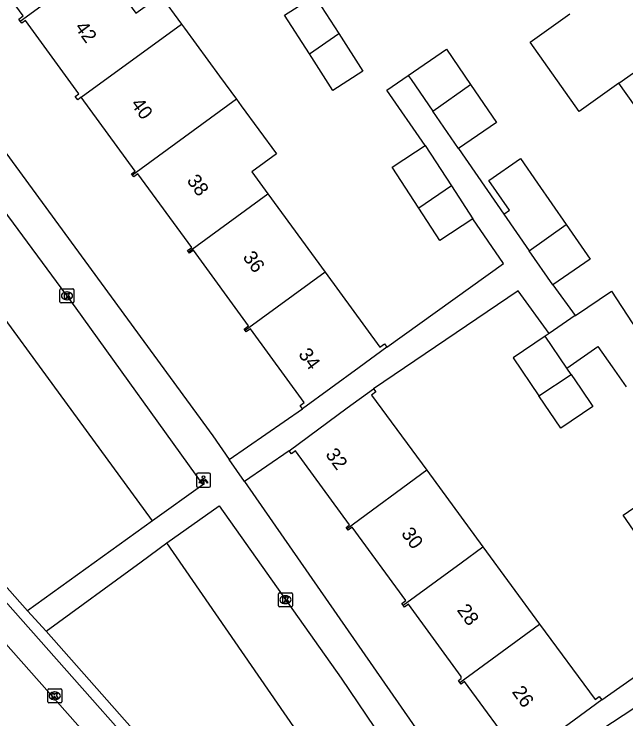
# Model space of a CAD drawing. Extents: x 157466 to 158888, y 383063 to 384677.
# Drawn here: x 157968.1 to 158011.8, y 383507.6 to 383558 of the extents above; entities that cross this region are included whole.
import ezdxf

# ---------------------------------------------------------------- set-up
doc = ezdxf.new("R2010")
doc.units = 0
for name, color, linetype in [('IMGEO_Groenvoorziening', 7, 'Continuous'), ('IMGEO_Kolk', 7, 'Continuous'), ('IMGEO_Lichtpunt', 7, 'Continuous'), ('IMGEO_Pand', 7, 'Continuous'), ('IMGEO_Pand_nummerreeks', 7, 'Continuous'), ('IMGEO_Rijbaan_lokaal_gesloten', 7, 'Continuous'), ('IMGEO_Voetpad_open', 7, 'Continuous')]:
    doc.layers.add(name, color=color, linetype=linetype)

msp = doc.modelspace()

# ---------------------------------------------------------------- linework, layer by layer
at = {"layer": 'IMGEO_Groenvoorziening'}
for points in [[(157977.961, 383521.773), (157959.54, 383546.985)], [(157993.986, 383498.111), (157992.947, 383500), (157978.989, 383520.199)]]:
    msp.add_lwpolyline(points, dxfattribs=at)
at = {"layer": 'IMGEO_Kolk'}
for p, q in [((157971.352, 383537.425), (157971.352, 383538.277)), ((157971.427, 383538.351), (157972.279, 383538.351)), ((157972.353, 383538.277), (157972.353, 383537.425)), ((157971.84, 383538.131), (157971.865, 383538.131)), ((157972.279, 383537.351), (157971.427, 383537.351)), ((157971.863, 383537.571), (157971.838, 383537.571)), ((157986.956, 383515.719), (157986.956, 383516.571)), ((157987.031, 383516.645), (157987.883, 383516.645)), ((157987.957, 383516.571), (157987.957, 383515.719)), ((157987.444, 383516.425), (157987.469, 383516.425)), ((157987.883, 383515.645), (157987.031, 383515.645)), ((157987.467, 383515.865), (157987.442, 383515.865)), ((157970.478, 383508.854), (157970.478, 383509.706)), ((157970.553, 383509.78), (157971.405, 383509.78)), ((157970.966, 383509.56), (157970.991, 383509.56)), ((157971.479, 383509.706), (157971.479, 383508.854)), ((157970.989, 383509), (157970.964, 383509)), ((157971.405, 383508.78), (157970.553, 383508.78))]:
    msp.add_line(p, q, dxfattribs=at)
for points in [[(157971.352, 383537.425), (157971.352, 383538.277)], [(157971.427, 383538.351), (157972.279, 383538.351)], [(157972.353, 383538.277), (157972.353, 383537.425)], [(157971.673, 383538.051), (157971.796, 383538.051), (157971.796, 383537.9), (157971.926, 383538.051), (157972.09, 383538.051), (157971.944, 383537.9), (157972.097, 383537.651), (157971.945, 383537.651), (157971.86, 383537.815), (157971.796, 383537.748), (157971.796, 383537.651), (157971.673, 383537.651), (157971.673, 383538.051)], [(157972.279, 383537.351), (157971.427, 383537.351)], [(157986.956, 383515.719), (157986.956, 383516.571)], [(157987.031, 383516.645), (157987.883, 383516.645)], [(157987.957, 383516.571), (157987.957, 383515.719)], [(157987.277, 383516.345), (157987.4, 383516.345), (157987.4, 383516.194), (157987.53, 383516.345), (157987.694, 383516.345), (157987.548, 383516.194), (157987.701, 383515.945), (157987.549, 383515.945), (157987.464, 383516.109), (157987.4, 383516.042), (157987.4, 383515.945), (157987.277, 383515.945), (157987.277, 383516.345)], [(157987.883, 383515.645), (157987.031, 383515.645)], [(157970.478, 383508.854), (157970.478, 383509.706)], [(157970.553, 383509.78), (157971.405, 383509.78)], [(157971.479, 383509.706), (157971.479, 383508.854)], [(157970.799, 383509.48), (157970.922, 383509.48), (157970.922, 383509.329), (157971.052, 383509.48), (157971.216, 383509.48), (157971.07, 383509.329), (157971.223, 383509.08), (157971.071, 383509.08), (157970.986, 383509.244), (157970.922, 383509.177), (157970.922, 383509.08), (157970.799, 383509.08), (157970.799, 383509.48)], [(157971.405, 383508.78), (157970.553, 383508.78)]]:
    msp.add_lwpolyline(points, dxfattribs=at)
for centre, start, end in [((157971.429, 383538.275), 91.552, 178.448), ((157971.429, 383538.275), 91.552, 178.448), ((157972.277, 383538.275), 1.552, 88.448), ((157972.277, 383538.275), 1.552, 88.448), ((157971.429, 383537.427), 181.552, 268.448), ((157971.429, 383537.427), 181.552, 268.448), ((157972.277, 383537.427), 271.552, 358.448), ((157972.277, 383537.427), 271.552, 358.448), ((157987.033, 383516.569), 91.552, 178.448), ((157987.033, 383516.569), 91.552, 178.448), ((157987.881, 383516.569), 1.552, 88.448), ((157987.881, 383516.569), 1.552, 88.448), ((157987.033, 383515.721), 181.552, 268.448), ((157987.033, 383515.721), 181.552, 268.448), ((157987.881, 383515.721), 271.552, 358.448), ((157987.881, 383515.721), 271.552, 358.448), ((157970.555, 383509.704), 91.552, 178.448), ((157970.555, 383509.704), 91.552, 178.448), ((157971.403, 383509.704), 1.552, 88.448), ((157971.403, 383509.704), 1.552, 88.448), ((157970.555, 383508.856), 181.552, 268.448), ((157970.555, 383508.856), 181.552, 268.448), ((157971.403, 383508.856), 271.552, 358.448), ((157971.403, 383508.856), 271.552, 358.448)]:
    msp.add_arc(centre, 0.0765, start, end, dxfattribs=at)
for centre, major_axis, ratio, start_param, end_param in [((157971.839, 383537.851), (-0.387, 0.002), 0.722429, 4.712389, 7.853982), ((157971.864, 383537.851), (-0.39, 0.002), 0.717154, 1.570796, 4.712389), ((157987.443, 383516.145), (-0.387, 0.002), 0.722429, 4.712389, 7.853982), ((157987.468, 383516.145), (-0.39, 0.002), 0.717154, 1.570796, 4.712389), ((157970.965, 383509.28), (-0.387, 0.002), 0.722429, 4.712389, 7.853982), ((157970.99, 383509.28), (-0.39, 0.002), 0.717154, 1.570796, 4.712389)]:
    msp.add_ellipse(centre, major_axis=major_axis, ratio=ratio, start_param=start_param, end_param=end_param, dxfattribs=at)
at = {"layer": 'IMGEO_Lichtpunt'}
for p, q in [((157981.109, 383525.094), (157981.109, 383524.287)), ((157981.109, 383525.094), (157981.109, 383524.287)), ((157982.011, 383525.189), (157981.203, 383525.189)), ((157982.011, 383525.189), (157981.203, 383525.189)), ((157982.105, 383524.287), (157982.105, 383525.094)), ((157982.105, 383524.287), (157982.105, 383525.094)), ((157981.203, 383524.193), (157982.011, 383524.193)), ((157981.203, 383524.193), (157982.011, 383524.193))]:
    msp.add_line(p, q, dxfattribs=at)
for points in [[(157981.483, 383524.758), (157981.522, 383524.73), (157981.334, 383524.468), (157981.296, 383524.495), (157981.483, 383524.758)], [(157981.585, 383524.71), (157981.632, 383524.71), (157981.632, 383524.388), (157981.585, 383524.388), (157981.585, 383524.71)], [(157981.695, 383524.73), (157981.733, 383524.757), (157981.92, 383524.495), (157981.881, 383524.467), (157981.695, 383524.73)]]:
    msp.add_lwpolyline(points, dxfattribs=at)
msp.add_circle((157981.608, 383524.892), 0.0994, dxfattribs=at)
for centre, start, end in [((157981.203, 383525.094), 90, 180), ((157981.203, 383525.094), 90, 180), ((157982.011, 383525.094), 0, 90), ((157982.011, 383525.094), 0, 90), ((157981.203, 383524.287), 180, 270), ((157981.203, 383524.287), 180, 270), ((157982.011, 383524.287), 270, 0), ((157982.011, 383524.287), 270, 360)]:
    msp.add_arc(centre, 0.0946, start, end, dxfattribs=at)
at = {"layer": 'IMGEO_Pand'}
for points in [[(157968.52, 383557.477), (157968.413, 383557.623), (157968.717, 383557.846), (157964.929, 383563.029), (157964.634, 383562.813), (157964.565, 383562.908)], [(157968.52, 383557.477), (157974.169, 383561.61)], [(157974.169, 383561.61), (157976.773, 383558.046), (157978.527, 383559.328), (157980.031, 383557.27)], [(157989.167, 383555.142), (157987.386, 383557.912), (157989.528, 383559.29)], [(157989.711, 383559.006), (157991.269, 383556.582)], [(158011.275, 383553.039), (158008.447, 383551.029), (158004.933, 383555.973), (158007.768, 383557.989)], [(157972.866, 383552.045), (157972.617, 383551.863), (157972.447, 383552.096), (157972.706, 383552.286), (157968.884, 383557.516), (157968.628, 383557.329), (157968.52, 383557.477)], [(157972.866, 383552.045), (157980.031, 383557.27)], [(157980.031, 383557.27), (157980.246, 383556.975), (157982.754, 383553.543), (157983.959, 383551.895)], [(158011.275, 383553.039), (158016.758, 383556.936)], [(157991.269, 383556.582), (157992.993, 383553.901), (157990.85, 383552.523), (157989.167, 383555.142)], [(157989.167, 383555.142), (157991.269, 383556.582)], [(157996.23, 383553.598), (157998.95, 383555.464), (158000.677, 383552.948)], [(157996.23, 383553.598), (157996.427, 383553.311), (157997.987, 383551.036)], [(157997.987, 383551.036), (158000.677, 383552.948)], [(158000.677, 383552.948), (158002.536, 383550.238), (157999.816, 383548.371)], [(158014.764, 383548.114), (158011.275, 383553.039)], [(157976.542, 383546.469), (157976.462, 383546.579), (157976.722, 383546.768), (157972.866, 383552.045)], [(157983.959, 383551.895), (157976.542, 383546.469)], [(157983.959, 383551.895), (157984.302, 383551.426), (157986.81, 383547.993), (157985.056, 383546.712), (157986.201, 383545.145)], [(157999.816, 383548.371), (157997.987, 383551.036)], [(157996.99, 383544.113), (157995.076, 383547.05), (157996.749, 383548.141), (157997.435, 383548.588)], [(157997.435, 383548.588), (157999.314, 383545.704)], [(158003.058, 383543.695), (158003.448, 383543.965), (158001.98, 383546.087), (158004.247, 383547.656), (158005.457, 383545.909), (158007.504, 383542.953)], [(157980.522, 383540.99), (157980.454, 383541.083), (157980.765, 383541.311), (157976.92, 383546.573), (157976.624, 383546.357), (157976.542, 383546.469)], [(157999.314, 383545.704), (157996.99, 383544.113)], [(157999.314, 383545.704), (158000.852, 383543.345)], [(157980.522, 383540.99), (157986.201, 383545.145)], [(157986.201, 383545.145), (157990.292, 383539.548)], [(158000.852, 383543.345), (157998.493, 383541.808), (157996.99, 383544.113)], [(158003.058, 383543.695), (158004.869, 383541.079)], [(158004.869, 383541.079), (158007.504, 383542.953)], [(158007.504, 383542.953), (158009.22, 383540.473), (158006.563, 383538.633)], [(157984.572, 383535.378), (157984.498, 383535.48), (157984.821, 383535.716), (157980.882, 383541.106), (157980.592, 383540.894), (157980.522, 383540.99)], [(158006.563, 383538.633), (158004.869, 383541.079)], [(157990.292, 383539.548), (157984.572, 383535.378)], [(157990.292, 383539.548), (157994.208, 383534.189), (157994.526, 383534.422), (157994.698, 383534.186)], [(158008.161, 383536.443), (158008.183, 383536.458), (158010.734, 383538.188), (158012.229, 383535.933), (158014.218, 383533.078)], [(158008.161, 383536.443), (158006.281, 383535.17)], [(157988.678, 383529.787), (157988.501, 383530.029), (157988.794, 383530.244), (157984.952, 383535.501), (157984.646, 383535.277), (157984.572, 383535.378)], [(158006.281, 383535.17), (158006, 383534.979)], [(158006, 383534.979), (158003.719, 383533.433), (158005.559, 383530.717)], [(158007.558, 383532.68), (158006, 383534.979)], [(157994.698, 383534.186), (157992.716, 383532.737), (157988.678, 383529.787)], [(158007.558, 383532.68), (158009.779, 383534.227), (158010.782, 383532.788), (158011.784, 383531.348)], [(158007.856, 383532.24), (158007.558, 383532.68)], [(158005.559, 383530.717), (158007.856, 383532.24)], [(158007.856, 383532.24), (158008.522, 383531.257), (158009.41, 383529.946), (158007.128, 383528.4), (158005.559, 383530.717)], [(157987.723, 383526.79), (157991.876, 383529.842), (157993.741, 383531.213)], [(157993.741, 383531.213), (157993.909, 383530.985), (157993.608, 383530.764), (157997.548, 383525.395)], [(157991.856, 383521.213), (157991.783, 383521.313), (157992.043, 383521.504), (157988.173, 383526.772), (157987.882, 383526.558), (157987.723, 383526.79)], [(157997.548, 383525.395), (157991.856, 383521.213)], [(157997.548, 383525.395), (158000, 383522.053), (158001.555, 383519.934)], [(158013.353, 383519.593), (158011.575, 383522.191), (158014.242, 383524.015)], [(157995.861, 383515.751), (157995.764, 383515.883), (157996.058, 383516.099), (157992.217, 383521.327), (157991.928, 383521.115), (157991.856, 383521.213)], [(157995.861, 383515.751), (158000, 383518.792), (158001.555, 383519.934)], [(158001.555, 383519.934), (158005.612, 383514.405)], [(157999.919, 383510.224), (157999.805, 383510.379), (158000, 383510.522), (158000, 383510.669), (157996.234, 383515.822), (157995.958, 383515.619), (157995.861, 383515.751)], [(157999.919, 383510.224), (158005.612, 383514.405)], [(158005.612, 383514.405), (158009.571, 383509.009), (158009.87, 383509.228), (158010.049, 383508.984)], [(158004.038, 383504.58), (158003.858, 383504.825), (158004.127, 383505.022), (158000.257, 383510.302), (158000, 383510.114), (157999.919, 383510.224)], [(158010.049, 383508.984), (158008.072, 383507.536), (158004.038, 383504.58)]]:
    msp.add_lwpolyline(points, dxfattribs=at)
at = {"layer": 'IMGEO_Rijbaan_lokaal_gesloten'}
msp.add_lwpolyline([(157992.101, 383485.193), (157928.672, 383556.808)], dxfattribs=at)
at = {"layer": 'IMGEO_Voetpad_open'}
for points in [[(157929.336, 383596.06), (157933.255, 383591.676), (157962.879, 383554.327), (157965.119, 383551.269), (157982.271, 383527.85), (157983.448, 383526.155)], [(157930.01, 383558.3), (157983.378, 383498.016), (157992.065, 383488.205), (157997.202, 383482.054), (158000.095, 383477.951)], [(157997.435, 383548.588), (157994.703, 383552.543), (157996.23, 383553.598)], [(157959.54, 383546.985), (157963.112, 383549.668), (157972.494, 383536.982), (157981.567, 383524.365), (157977.961, 383521.773)], [(157999.816, 383548.371), (158003.058, 383543.695)], [(157994.698, 383534.186), (158003.037, 383540.171), (158000.852, 383543.345)], [(157969.04, 383515.361), (157948.437, 383538.644)], [(158006.281, 383535.17), (158004.089, 383538.223), (157993.741, 383531.213)], [(158006.563, 383538.633), (158008.161, 383536.443)], [(157983.448, 383526.155), (157988.678, 383529.787)], [(157987.723, 383526.79), (157984.541, 383524.581)], [(157984.541, 383524.581), (157983.448, 383526.155)], [(157984.541, 383524.581), (158000.328, 383501.854)], [(157978.989, 383520.199), (157982.718, 383522.845), (157991.425, 383510.532), (157998.027, 383500.773), (157996.836, 383500), (157993.986, 383498.111)], [(157977.961, 383521.773), (157969.04, 383515.361)], [(157970.368, 383513.905), (157977.144, 383518.851), (157978.989, 383520.199)], [(158010.049, 383508.984), (158019.772, 383515.834), (158017.816, 383518.792)], [(157970.368, 383513.905), (157969.04, 383515.361)], [(157987.894, 383494.074), (157970.368, 383513.905)], [(158012.33, 383508.373), (158009.303, 383506.368)]]:
    msp.add_lwpolyline(points, dxfattribs=at)

# ---------------------------------------------------------------- texts
at = {"layer": 'IMGEO_Pand_nummerreeks'}
for s, rotation, p in [('42', 306.1649, (157972.37, 383557.024)), ('40', 306.1649, (157976.372, 383551.548)), ('38', 306.1649, (157980.372, 383546.077)), ('36', 306.1665, (157984.368, 383540.607)), ('34', 306.3393, (157988.337, 383533.671)), ('32', 306.2756, (157990.275, 383526.523)), ('30', 306.3046, (157995.683, 383520.869)), ('28', 306.1607, (157999.666, 383515.399)), ('26', 305.3003, (158003.598, 383509.562))]:
    msp.add_text(s, height=1, rotation=rotation, dxfattribs=at).set_placement(p)

doc.saveas('drawing.dxf')
